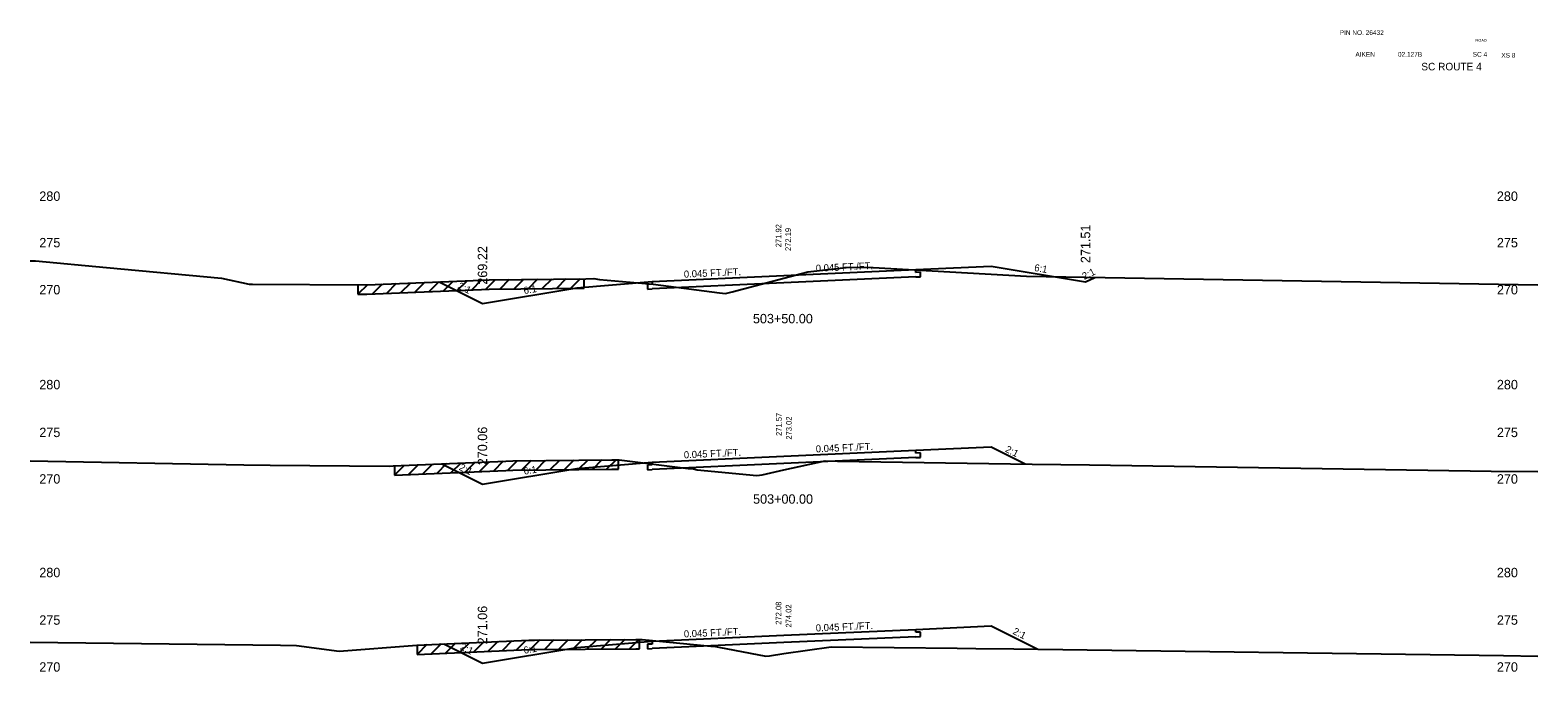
# Model space of a CAD drawing. Extents: x 883 to 1160, y 1002 to 4323.
# Drawn here: x 1000 to 1160, y 1840.1 to 1908.2 of the extents above; entities that cross this region are included whole.
import ezdxf

# ---------------------------------------------------------------- set-up
doc = ezdxf.new("R2010")
doc.units = 0
for name, color, linetype in [('Level 1', 7, 'Continuous'), ('Level 10', 7, 'Continuous'), ('Level 11', 7, 'Continuous'), ('Level 12', 7, 'Continuous'), ('Level 3', 7, 'Continuous'), ('Level 32', 7, 'Continuous'), ('Level 33', 7, 'Continuous'), ('Level 59', 7, 'Continuous'), ('Level 6', 7, 'Continuous'), ('Level 60', 7, 'Continuous'), ('Level 61', 7, 'Continuous'), ('Level 7', 7, 'Continuous')]:
    doc.layers.add(name, color=color, linetype=linetype)

msp = doc.modelspace()

# ---------------------------------------------------------------- linework, layer by layer
at = {"layer": 'Level 11'}
for p, q in [((1094, 1882.52), (1094, 1882.82)), ((1094.5, 1882.54), (1094, 1882.52)), ((1094, 1882.04), (1094.5, 1882.06)), ((1094.5, 1882.06), (1094.5, 1882.54)), ((1066, 1881.26), (1065.5, 1881.24)), ((1065.5, 1881.24), (1065.5, 1880.76)), ((1065.5, 1880.76), (1066, 1880.78)), ((1066, 1881.56), (1066, 1881.26)), ((1094, 1863.35), (1094, 1863.65)), ((1094.5, 1863.37), (1094, 1863.35)), ((1094, 1862.87), (1094.5, 1862.89)), ((1094.5, 1862.89), (1094.5, 1863.37)), ((1066, 1862.09), (1065.5, 1862.07)), ((1065.5, 1862.07), (1065.5, 1861.59)), ((1065.5, 1861.59), (1066, 1861.61)), ((1066, 1862.39), (1066, 1862.09)), ((1066, 1843.39), (1066, 1843.09)), ((1094, 1844.35), (1094, 1844.65)), ((1094.5, 1844.37), (1094, 1844.35)), ((1094, 1843.87), (1094.5, 1843.89)), ((1094.5, 1843.89), (1094.5, 1844.37)), ((1066, 1843.09), (1065.5, 1843.07)), ((1065.5, 1843.07), (1065.5, 1842.59)), ((1065.5, 1842.59), (1066, 1842.61))]:
    msp.add_line(p, q, dxfattribs=at)
at = {"layer": 'Level 12'}
for p, q in [((1094, 1882.04), (1080, 1881.41)), ((1080, 1881.41), (1066, 1880.78)), ((1094, 1862.87), (1080, 1862.24)), ((1080, 1862.24), (1066, 1861.61)), ((1080, 1843.24), (1066, 1842.61)), ((1094, 1843.87), (1080, 1843.24))]:
    msp.add_line(p, q, dxfattribs=at)
at = {"layer": 'Level 59'}
for p, q in [((1066, 1881.56), (1080, 1882.19)), ((1080, 1882.19), (1094, 1882.82)), ((1066, 1862.39), (1080, 1863.02)), ((1080, 1863.02), (1094, 1863.65)), ((1066, 1843.39), (1080, 1844.02)), ((1080, 1844.02), (1094, 1844.65))]:
    msp.add_line(p, q, dxfattribs=at)
at = {"layer": 'Level 6'}
for p, q in [((1094, 1882.82), (1102, 1883.18)), ((1058, 1880.89), (1066, 1881.56)), ((1094, 1863.65), (1102, 1864.01)), ((1058, 1861.72), (1066, 1862.39)), ((1094, 1844.65), (1102, 1845.01)), ((1058, 1842.72), (1066, 1843.39))]:
    msp.add_line(p, q, dxfattribs=at)
at = {"layer": 'Level 60'}
for p, q in [((1000, 1883.75), (1000.01, 1883.75)), ((1000.01, 1883.75), (1000.56, 1883.75)), ((1000.56, 1883.75), (1008.09, 1883.05)), ((1008.09, 1883.05), (1020.31, 1881.92)), ((1020.31, 1881.92), (1023.23, 1881.28)), ((1035.72, 1881.2), (1047.89, 1881.7)), ((1047.89, 1881.7), (1048.71, 1881.73)), ((1048.71, 1881.73), (1058.96, 1881.85)), ((1058.96, 1881.85), (1059.81, 1881.86)), ((1059.81, 1881.86), (1060.41, 1881.78)), ((1060.41, 1881.78), (1066.11, 1881.27)), ((1074.5, 1880.46), (1080, 1881.92)), ((1080, 1881.92), (1082.53, 1882.59)), ((1082.53, 1882.59), (1086.9, 1883.09)), ((1086.9, 1883.09), (1089.46, 1883.05)), ((1089.46, 1883.05), (1105.75, 1882.12)), ((1105.75, 1882.12), (1112.01, 1882.01)), ((1112.01, 1882.01), (1160, 1881.21)), ((1023.23, 1881.28), (1023.61, 1881.28)), ((1023.61, 1881.28), (1035.72, 1881.2)), ((1066.11, 1881.27), (1073.14, 1880.37)), ((1073.14, 1880.37), (1073.79, 1880.3)), ((1073.79, 1880.3), (1074.5, 1880.46)), ((1000, 1862.53), (1022.69, 1862.11)), ((1038.54, 1862), (1050.49, 1862.5)), ((1050.49, 1862.5), (1051.21, 1862.53)), ((1051.21, 1862.53), (1061.72, 1862.63)), ((1061.72, 1862.63), (1062.5, 1862.63)), ((1062.5, 1862.63), (1069.84, 1861.72)), ((1080, 1861.57), (1084.36, 1862.53)), ((1084.36, 1862.53), (1085.69, 1862.51)), ((1085.69, 1862.51), (1106.34, 1862.19)), ((1022.69, 1862.11), (1025.48, 1862.06)), ((1025.48, 1862.06), (1038.11, 1861.97)), ((1038.11, 1861.97), (1038.54, 1862)), ((1069.84, 1861.72), (1070.41, 1861.67)), ((1070.41, 1861.67), (1070.8, 1861.59)), ((1070.8, 1861.59), (1077.12, 1860.98)), ((1077.12, 1860.98), (1077.7, 1861.06)), ((1077.7, 1861.06), (1080, 1861.57)), ((1106.34, 1862.19), (1112.41, 1862.11)), ((1112.41, 1862.11), (1155.04, 1861.43)), ((1155.04, 1861.43), (1160, 1861.39)), ((1000, 1843.3), (1026.58, 1842.98)), ((1041.04, 1842.99), (1052.91, 1843.5)), ((1052.91, 1843.5), (1053.54, 1843.52)), ((1053.54, 1843.52), (1064.28, 1843.57)), ((1064.28, 1843.57), (1064.94, 1843.58)), ((1064.94, 1843.58), (1072.25, 1842.87)), ((1026.58, 1842.98), (1028.25, 1842.94)), ((1028.25, 1842.94), (1032.8, 1842.34)), ((1032.8, 1842.34), (1041.04, 1842.99)), ((1072.25, 1842.87), (1072.73, 1842.83)), ((1072.73, 1842.83), (1073.08, 1842.75)), ((1073.08, 1842.75), (1078.07, 1841.8)), ((1078.07, 1841.8), (1078.45, 1841.85)), ((1078.45, 1841.85), (1080, 1842.08)), ((1080, 1842.08), (1085, 1842.79)), ((1085, 1842.79), (1098.36, 1842.67)), ((1098.36, 1842.67), (1100.35, 1842.61)), ((1100.35, 1842.61), (1104.38, 1842.59)), ((1104.38, 1842.59), (1156.36, 1841.89)), ((1156.36, 1841.89), (1160, 1841.82))]:
    msp.add_line(p, q, dxfattribs=at)
at = {"layer": 'Level 61'}
for p, q in [((1046.37, 1881.64), (1045.32, 1880.59)), ((1047.87, 1881.7), (1046.82, 1880.65)), ((1049.35, 1881.74), (1048.33, 1880.72)), ((1050.85, 1881.76), (1049.83, 1880.74)), ((1052.35, 1881.77), (1051.34, 1880.76)), ((1053.85, 1881.79), (1052.84, 1880.78)), ((1055.36, 1881.81), (1054.34, 1880.8)), ((1056.86, 1881.83), (1055.85, 1880.81)), ((1058.37, 1881.84), (1057.35, 1880.83)), ((1058.78, 1880.85), (1058.78, 1881.85)), ((1035.79, 1881.2), (1034.79, 1880.2)), ((1034.79, 1881.2), (1034.79, 1880.2)), ((1034.79, 1880.2), (1035.72, 1880.2)), ((1035.72, 1880.2), (1047.89, 1880.7)), ((1037.34, 1881.26), (1036.3, 1880.22)), ((1038.85, 1881.33), (1037.8, 1880.28)), ((1040.35, 1881.39), (1039.3, 1880.35)), ((1041.85, 1881.45), (1040.81, 1880.41)), ((1043.36, 1881.51), (1042.31, 1880.47)), ((1044.86, 1881.57), (1043.82, 1880.53)), ((1047.89, 1880.7), (1048.71, 1880.73)), ((1048.71, 1880.73), (1058.78, 1880.85)), ((1048.7, 1862.42), (1047.66, 1861.38)), ((1050.2, 1862.48), (1049.16, 1861.44)), ((1051.69, 1862.53), (1050.66, 1861.5)), ((1053.17, 1862.55), (1052.16, 1861.54)), ((1054.67, 1862.56), (1053.66, 1861.55)), ((1056.17, 1862.58), (1055.16, 1861.57)), ((1057.68, 1862.59), (1056.66, 1861.58)), ((1059.18, 1862.61), (1058.17, 1861.6)), ((1060.68, 1862.62), (1059.67, 1861.61)), ((1062.18, 1862.63), (1061.17, 1861.63)), ((1062.42, 1861.63), (1062.42, 1862.63)), ((1039.69, 1862.05), (1038.65, 1861.01)), ((1038.65, 1862.01), (1038.65, 1861.01)), ((1038.65, 1861.01), (1050.49, 1861.5)), ((1041.19, 1862.11), (1040.15, 1861.07)), ((1042.7, 1862.17), (1041.65, 1861.13)), ((1044.2, 1862.24), (1043.15, 1861.19)), ((1045.7, 1862.3), (1044.65, 1861.25)), ((1047.2, 1862.36), (1046.16, 1861.32)), ((1050.49, 1861.5), (1051.21, 1861.53)), ((1051.21, 1861.53), (1061.72, 1861.63)), ((1061.72, 1861.63), (1062.42, 1861.63)), ((1046.61, 1843.23), (1045.57, 1842.18)), ((1048.12, 1843.29), (1047.07, 1842.25)), ((1049.62, 1843.36), (1048.57, 1842.31)), ((1051.12, 1843.42), (1050.08, 1842.37)), ((1052.62, 1843.48), (1051.58, 1842.44)), ((1054.1, 1843.53), (1053.08, 1842.5)), ((1055.59, 1843.53), (1054.58, 1842.53)), ((1057.09, 1843.54), (1056.09, 1842.54)), ((1058.59, 1843.55), (1057.59, 1842.54)), ((1060.1, 1843.55), (1059.09, 1842.55)), ((1061.6, 1843.56), (1060.59, 1842.55)), ((1063.1, 1843.57), (1062.09, 1842.56)), ((1064.6, 1843.57), (1063.6, 1842.57)), ((1064.68, 1842.57), (1064.68, 1843.57)), ((1042.11, 1843.03), (1041.06, 1841.99)), ((1041.06, 1842.99), (1041.06, 1841.99)), ((1041.06, 1841.99), (1052.91, 1842.5)), ((1043.61, 1843.1), (1042.56, 1842.05)), ((1045.11, 1843.16), (1044.07, 1842.12)), ((1052.91, 1842.5), (1053.54, 1842.52)), ((1053.54, 1842.52), (1064.28, 1842.57)), ((1064.28, 1842.57), (1064.68, 1842.57))]:
    msp.add_line(p, q, dxfattribs=at)
at = {"layer": 'Level 7'}
for p, q in [((1102, 1883.18), (1112, 1881.51)), ((1112, 1881.51), (1112.97, 1882)), ((1043.42, 1881.51), (1048, 1879.22)), ((1048, 1879.22), (1058, 1880.89)), ((1102, 1864.01), (1105.61, 1862.2)), ((1043.69, 1862.21), (1048, 1860.06)), ((1048, 1860.06), (1058, 1861.72)), ((1102, 1845.01), (1106.92, 1842.55)), ((1043.9, 1843.11), (1048, 1841.06)), ((1048, 1841.06), (1058, 1842.72))]:
    msp.add_line(p, q, dxfattribs=at)

# ---------------------------------------------------------------- texts
at = {"layer": 'Level 1'}
for s, height, p in [('PIN NO. 26432', 0.5, (1138.97, 1907.72)), ('AIKEN', 0.5, (1140.64, 1905.41)), ('02.127B', 0.5, (1145.15, 1905.41)), ('SC 4', 0.5, (1153.09, 1905.41)), ('XS 8', 0.5, (1156.12, 1905.31)), ('SC ROUTE 4', 0.8, (1147.63, 1903.96)), ('503+50.00', 1, (1076.7, 1877.12)), ('503+00.00', 1, (1076.72, 1857.98))]:
    msp.add_text(s, height=height, dxfattribs=at).set_placement(p)
at = {"layer": 'Level 10'}
for s, p in [('271.92', (1079.72, 1885.19)), ('271.57', (1079.76, 1865.17)), ('272.08', (1079.72, 1845.14))]:
    msp.add_text(s, height=0.6, rotation=90, dxfattribs=at).set_placement(p)
at = {"layer": 'Level 3'}
for s, height, p in [('ROAD', 0.3, (1153.38, 1906.99)), (' 280', 1, (1000.6, 1890.11)), (' 280', 1, (1155.28, 1890.11)), (' 275', 1, (1000.6, 1885.18)), (' 275', 1, (1155.28, 1885.18)), (' 270', 1, (1000.6, 1880.19)), (' 270', 1, (1155.28, 1880.19)), (' 280', 1, (1000.6, 1870.12)), (' 280', 1, (1155.28, 1870.12)), (' 275', 1, (1000.6, 1865.05)), (' 275', 1, (1155.28, 1865.05)), (' 270', 1, (1000.6, 1860.11)), (' 270', 1, (1155.28, 1860.11)), (' 280', 1, (1000.6, 1850.18)), (' 280', 1, (1155.28, 1850.18)), (' 275', 1, (1000.6, 1845.14)), (' 275', 1, (1155.28, 1845.14)), (' 270', 1, (1000.6, 1840.16)), (' 270', 1, (1155.28, 1840.16))]:
    msp.add_text(s, height=height, dxfattribs=at).set_placement(p)
at = {"layer": 'Level 32'}
for s, rotation, p in [('0.045 FT./FT.', 2.5766, (1083.39, 1882.59)), ('6:1', 350.5377, (1106.52, 1882.68)), ('0.045 FT./FT.', 2.5766, (1069.39, 1881.96)), ('2:1', 26.5651, (1111.87, 1881.72)), ('2:1', 333.435, (1045.31, 1880.85)), ('6:1', 9.4623, (1052.43, 1880.22)), ('0.045 FT./FT.', 2.5766, (1083.39, 1863.42)), ('2:1', 333.435, (1103.41, 1863.52)), ('0.045 FT./FT.', 2.5766, (1069.39, 1862.79)), ('2:1', 333.435, (1045.45, 1861.61)), ('6:1', 9.4623, (1052.43, 1861.05)), ('0.045 FT./FT.', 2.5766, (1069.39, 1843.79)), ('0.045 FT./FT.', 2.5766, (1083.39, 1844.42)), ('2:1', 333.435, (1104.21, 1844.2)), ('2:1', 333.435, (1045.55, 1842.56)), ('6:1', 9.4623, (1052.43, 1842.05))]:
    msp.add_text(s, height=0.75, rotation=rotation, dxfattribs=at).set_placement(p)
at = {"layer": 'Level 33'}
for s, p in [('271.51', (1112.5, 1883.51)), ('269.22', (1048.5, 1881.22)), ('270.06', (1048.5, 1862.06)), ('271.06', (1048.5, 1843.06))]:
    msp.add_text(s, height=1, rotation=90, dxfattribs=at).set_placement(p)
at = {"layer": 'Level 59'}
for s, p in [(' 272.19', (1080.74, 1884.57)), (' 273.02', (1080.82, 1864.56)), (' 274.02', (1080.79, 1844.62))]:
    msp.add_text(s, height=0.6, rotation=90, dxfattribs=at).set_placement(p)

doc.saveas('drawing.dxf')
